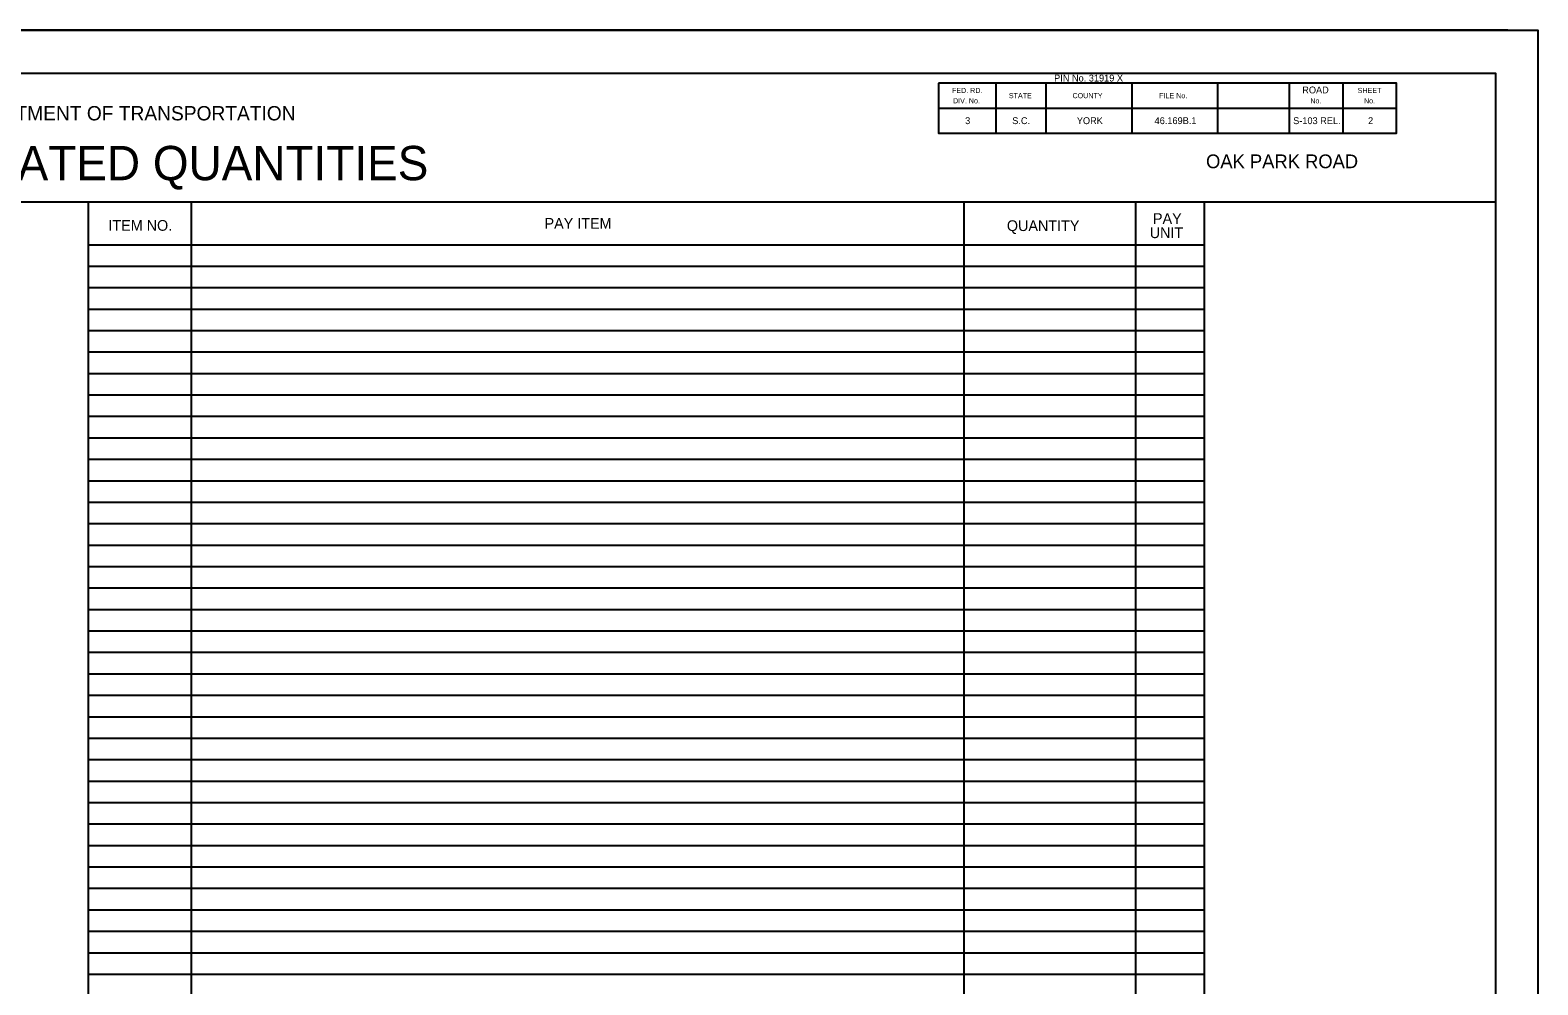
# Model space of a CAD drawing. Extents: x -796 to 2793, y -4650 to 4425.
# Drawn here: x 1899 to 2777, y -706 to -150 of the extents above; entities that cross this region are included whole.
import ezdxf

# ---------------------------------------------------------------- set-up
doc = ezdxf.new("R2010")
doc.units = 0
for name, color, linetype in [('RD_HC_CL', 7, 'Continuous'), ('RD_HC_Data', 7, 'Continuous'), ('RD_HC_Data_Tic', 7, 'Continuous')]:
    doc.layers.add(name, color=color, linetype=linetype)

msp = doc.modelspace()

# ---------------------------------------------------------------- linework, layer by layer
at = {"layer": 'RD_HC_CL'}
msp.add_lwpolyline([(981.41, -150), (2777.4, -150), (2777.4, -1250), (981.41, -1250)], close=True, dxfattribs=at)
at = {"layer": 'RD_HC_Data'}
for p, q in [((2760, -150), (1000, -150)), ((2760, -150), (1000, -150)), ((1915.25, -175), (1915.25, -174.95)), ((2752.75, -175), (2752.75, -242.85)), ((2461.65, -180.85), (2461.65, -195.45)), ((2490.85, -180.85), (2490.85, -195.45)), ((2540.85, -180.85), (2540.85, -195.45)), ((2590.85, -180.85), (2590.85, -195.45)), ((2632.5, -180.85), (2632.5, -195.45)), ((2663.75, -180.85), (2663.75, -195.45)), ((2428.35, -195.45), (2695, -195.45)), ((2461.65, -195.45), (2461.65, -210.05)), ((2490.85, -195.45), (2490.85, -210.05)), ((2540.85, -195.45), (2540.85, -210.05)), ((2590.85, -195.45), (2590.85, -210.05)), ((2632.5, -195.45), (2632.5, -210.05)), ((2663.75, -195.45), (2663.75, -210.05)), ((1627.75, -250), (2752.75, -250)), ((1932.95, -250), (1932.95, -1225)), ((1992.95, -250), (1992.95, -1225)), ((2442.95, -250), (2442.95, -1225)), ((2542.95, -250), (2542.95, -1225)), ((2582.95, -250), (2582.95, -1225)), ((1932.95, -275), (2582.95, -275)), ((1932.95, -287.5), (2582.95, -287.5)), ((1932.95, -300), (2582.95, -300)), ((1932.95, -312.5), (2582.95, -312.5)), ((1932.95, -325), (2582.95, -325)), ((1932.95, -337.5), (2582.95, -337.5)), ((1932.95, -350), (2582.95, -350)), ((1932.95, -362.5), (2582.95, -362.5)), ((1932.95, -375), (2582.95, -375)), ((1932.95, -387.5), (2582.95, -387.5)), ((1932.95, -400), (2582.95, -400)), ((1932.95, -412.5), (2582.95, -412.5)), ((1932.95, -425), (2582.95, -425)), ((1932.95, -437.5), (2582.95, -437.5)), ((1932.95, -450), (2582.95, -450)), ((1932.95, -462.5), (2582.95, -462.5)), ((1932.95, -475), (2582.95, -475)), ((1932.95, -487.5), (2582.95, -487.5)), ((1932.95, -500), (2582.95, -500)), ((1932.95, -512.5), (2582.95, -512.5)), ((1932.95, -525), (2582.95, -525)), ((1932.95, -537.5), (2582.95, -537.5)), ((1932.95, -550), (2582.95, -550)), ((1932.95, -562.5), (2582.95, -562.5)), ((1932.95, -575), (2582.95, -575)), ((1932.95, -587.5), (2582.95, -587.5)), ((1932.95, -600), (2582.95, -600)), ((1932.95, -612.5), (2582.95, -612.5)), ((1932.95, -625), (2582.95, -625)), ((1932.95, -637.5), (2582.95, -637.5)), ((1932.95, -650), (2582.95, -650)), ((1932.95, -662.5), (2582.95, -662.5)), ((1932.95, -675), (2582.95, -675)), ((1932.95, -687.5), (2582.95, -687.5)), ((1932.95, -700), (2582.95, -700))]:
    msp.add_line(p, q, dxfattribs=at)
for points in [[(1077.75, -175), (2752.75, -175), (2752.75, -1225), (1077.75, -1225)], [(2428.35, -180.85), (2428.35, -210.05), (2695, -210.05), (2695, -180.85)]]:
    msp.add_lwpolyline(points, close=True, dxfattribs=at)

# ---------------------------------------------------------------- texts
at = {"layer": 'RD_HC_Data_Tic'}
for s, height, p in [('FED. RD.', 3, (2436.12, -186.65)), ('PIN No. 31919 X   ', 4, (2495.62, -179.93)), ('      ROAD      ', 4, (2631.25, -186.85)), ('SHEET', 3, (2672.46, -186.65)), ('DIV. No.', 3, (2436.74, -192.65)), ('STATE', 3, (2469.27, -189.65)), ('COUNTY', 3, (2506.34, -189.65)), ('FILE No.', 3, (2556.85, -189.65)), ('No.', 3, (2644.88, -192.65)), ('No.', 3, (2676.13, -192.65)), ('SOUTH CAROLINA DEPARTMENT OF TRANSPORTATION', 8.3499, (1749.79, -202.58)), ('3', 4, (2443.8, -204.75)), ('S.C.', 4, (2471.23, -204.75)), ('      YORK      ', 4, (2499.93, -204.75)), ('   46.169B.1    ', 4, (2549.69, -204.75)), ('   S-103 REL.  ', 4, (2630.41, -204.75)), ('       2        ', 4, (2668.11, -204.75)), ('SUMMARY OF ESTIMATED QUANTITIES ', 20, (1621.44, -237.45)), ('OAK PARK ROAD                 ', 8, (2584.12, -230.43)), ('ITEM NO.', 6.25, (1944.75, -266.9)), ('PAY ITEM', 6.25, (2198.8, -265.7)), ('QUANTITY', 6.25, (2468.11, -267.05)), ('PAY', 6.25, (2553.21, -262.92)), ('UNIT', 6.25, (2551.32, -271.17))]:
    msp.add_text(s, height=height, dxfattribs=at).set_placement(p)

doc.saveas('drawing.dxf')
